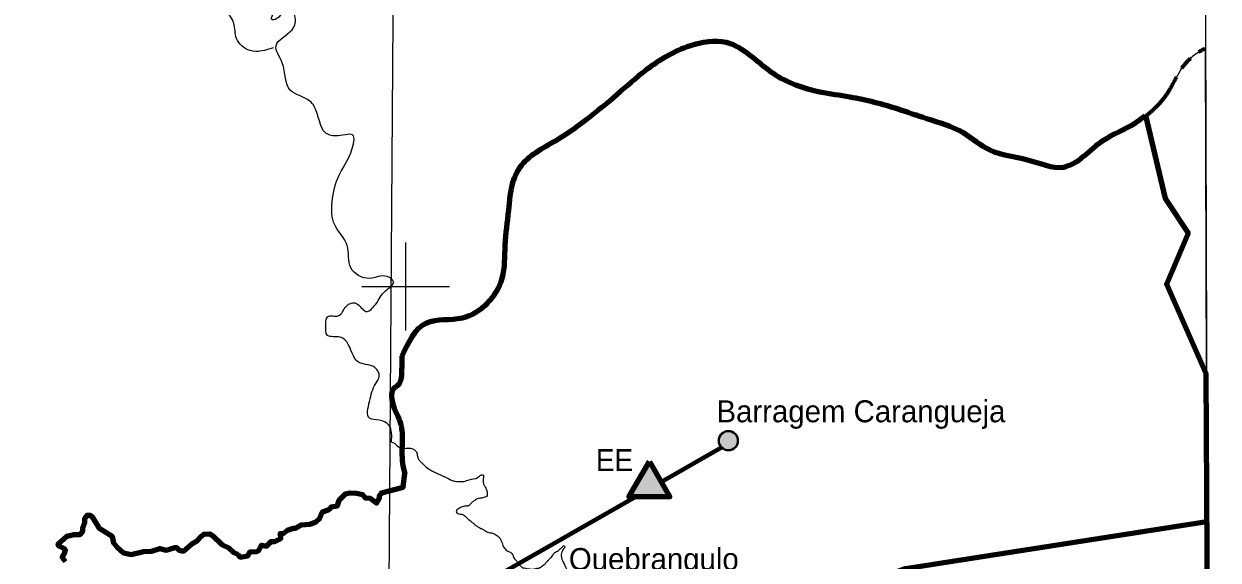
# Model space of a CAD drawing. Extents: x 553962 to 842807, y 8883888 to 9032388.
# Drawn here: x 766307 to 793496, y 8968776 to 8980977 of the extents above; entities that cross this region are included whole.
import ezdxf

# ---------------------------------------------------------------- set-up
doc = ezdxf.new("R2010")
doc.units = 0
doc.header["$LTSCALE"] = 200
doc.linetypes.add('LONG_DASH_SHORT_DASH', pattern=[9.9, 6, -1.2, 1.5, -1.2])
for name, color, linetype, lineweight in [('1', 7, 'Continuous', 13), ('2', 7, 'Continuous', 13), ('24', 7, 'Continuous', 25), ('28', 7, 'Continuous', 40), ('3', 7, 'Continuous', 13), ('41', 7, 'Continuous', 40), ('57', 7, 'Continuous', 13), ('7', 7, 'LONG_DASH_SHORT_DASH', 60), ('9', 7, 'Continuous', 90)]:
    doc.layers.add(name, color=color, linetype=linetype, lineweight=lineweight)

msp = doc.modelspace()

# ---------------------------------------------------------------- hatches: boundary and pattern name
at = {"layer": '28'}
msp.add_hatch(color=256, dxfattribs=at).paths.add_polyline_path([(780547.1, 8971019.7), (781013.2, 8970212.3), (780081, 8970212.3)])
at = {"layer": '41'}
msp.add_hatch(color=256, dxfattribs=at).paths.add_polyline_path([(782565, 8971494.2, 1), (782127.4, 8971494.2, 1)])

# ---------------------------------------------------------------- linework, layer by layer
at = {"layer": '1'}
msp.add_lwpolyline([(774987.1, 9020818), (774482.3, 8948876), (774053.6, 8890875.3)], dxfattribs=at)
at = {"layer": '2'}
for p, q in [((775000, 8974000), (775000, 8976000)), ((774000, 8975000), (776000, 8975000))]:
    msp.add_line(p, q, dxfattribs=at)
at = {"layer": '24'}
for points in [[(771983.6, 8980431.6), (771458.1, 8980369.7), (771148.9, 8980648.1), (771087.1, 8980988.4), (770932.5, 8981297.7), (770808.9, 8981638), (770345.2, 8981761.8), (770005.1, 8981885.5), (769819.6, 8982071.1), (769634.1, 8981854.6), (769479.5, 8982009.2), (769015.8, 8982318.6), (768923.1, 8982689.8), (768706.7, 8982937.2), (768593.5, 8983157.4), (768713.2, 8983415.3), (768842, 8983516.6), (768842, 8983590.2), (768630.3, 8983700.8), (768289.8, 8983940.2), (768207, 8984262.5), (768022.9, 8984465.2), (767700.8, 8984557.2), (767590.3, 8984640.1), (767553.5, 8985036.1), (767599.5, 8985266.4), (767599.5, 8985422.9), (767461.5, 8985607.1), (767314.2, 8985634.8), (767268.2, 8985533.4), (767139.4, 8985496.6), (766918.5, 8985616.3), (766789.6, 8985818.9), (766559.5, 8985957.1), (766219, 8986297.8), (765850.9, 8986500.4), (765363.1, 8986924.1), (764801.7, 8987504.3), (764663.6, 8987624), (764378.3, 8988066), (764295.5, 8988259.4), (764221.8, 8988296.3), (764083.8, 8988204.2), (763982.5, 8988268.6), (763669.6, 8988664.7), (763586.8, 8988683.1), (763540.8, 8988848.8), (763605.2, 8988913.3), (763665, 8988922.5), (763720.2, 8989088.3), (763554.6, 8989254.1), (763480.9, 8989475.1), (763628.2, 8989677.7), (763977.9, 8989935.6), (764143.6, 8990101.3), (764125.2, 8990285.5), (763849.1, 8990377.6), (763793.9, 8990525), (763591.4, 8990617.1), (763480.9, 8990635.5), (763260.1, 8990525), (763094.4, 8990525), (762965.5, 8990635.5), (762818.3, 8990856.5), (762781.5, 8990930.2), (762652.6, 8990967), (762450.1, 8991169.6), (762082, 8991335.4), (761916.3, 8991464.3), (761750.7, 8991464.3), (761640.2, 8991261.7), (761456.2, 8991059.1), (761382.5, 8990967), (761290.5, 8990948.6), (761198.5, 8991059.1), (761143.2, 8991298.6), (760867.1, 8991464.3), (760738.3, 8991666.9), (760499, 8991795.9), (760351.7, 8992035.3), (760094, 8992495.8), (759854.7, 8992403.7), (759652.3, 8992256.3), (759394.6, 8992477.3), (758971.2, 8992643.1), (758731.9, 8992753.6), (758639.9, 8993048.3), (758566.2, 8993324.6), (758695.1, 8993508.8), (758916, 8993453.6), (758879.2, 8993619.3)], [(774675.9, 8971457.7), (774621.3, 8971839.9), (774398.4, 8971961.6), (774175.5, 8972002.1), (774175.5, 8972387.4), (774317.3, 8972793), (774398.4, 8972955.3), (774297.1, 8973158.1), (773891.7, 8973300), (773810.7, 8973421.7), (773506.6, 8973847.6), (773222.9, 8973888.2), (773182.4, 8974151.8), (773222.9, 8974314), (773466.1, 8974334.3), (773648.5, 8974557.4), (773871.5, 8974618.2), (774094.4, 8974435.7), (774317.3, 8974598), (774540.3, 8974902.2), (774722.7, 8975105), (774580.8, 8975226.6), (774175.5, 8975186.1), (773749.8, 8975429.4), (773668.8, 8975936.4), (773385, 8976402.9), (773324.2, 8976930.1), (773486.4, 8977538.5), (773810.7, 8978248.3), (773810.7, 8978430.9), (773466.1, 8978430.9), (773182.4, 8978491.7), (772918.9, 8979100.1), (772817.6, 8979221.8), (772371.7, 8979465.1), (772189.3, 8980093.8), (772047.4, 8980479.1), (772412.2, 8980844.2), (772473, 8981168.7), (772331.2, 8981371.5), (772108.2, 8981128.1), (771966.3, 8981067.3), (772108.2, 8981452.6), (772189.3, 8981756.8), (772250.1, 8981979.9), (772392, 8982081.3), (772432.5, 8982324.6), (772229.8, 8982466.6), (772189.3, 8982730.2), (772432.5, 8982933), (772392, 8983196.7), (772250.1, 8983338.6), (772067.7, 8983500.8), (771824.5, 8983602.2), (771844.8, 8983865.9), (772432.5, 8984068.7), (772716.2, 8984109.2), (772979.7, 8984129.5), (773081, 8984332.3), (773486.4, 8984596), (773932.3, 8984839.3), (773932.3, 8985062.4), (773830.9, 8985244.9), (773830.9, 8985488.3), (774175.5, 8985812.8), (774337.6, 8985934.5), (774195.7, 8986117), (774114.7, 8986340.1), (773830.9, 8986299.5), (773668.8, 8986238.7), (773304, 8986380.6), (773141.8, 8986867.3), (773364.8, 8987475.7), (773405.3, 8987840.8), (773202.6, 8988205.8), (772939.2, 8988327.5), (772716.2, 8988570.8), (772777, 8988793.9), (773081, 8988854.8), (773324.2, 8988956.2), (773526.9, 8989098.1), (773385, 8989605.1), (773283.7, 8989970.2), (773000, 8990152.7), (772858.1, 8990436.6), (772979.7, 8990720.5), (772878.4, 8990761.1), (772493.3, 8990821.9), (772351.4, 8990963.9), (772047.4, 8991004.4), (771844.7, 8991166.7)], [(774675.9, 8971457.7), (774738.3, 8971438.3), (774783.6, 8971397.1), (774879.5, 8971329.9), (774915, 8971319.3), (775042.2, 8971323.1), (775133.7, 8971317), (775179.3, 8971301.3), (775209.5, 8971275.5), (775229.7, 8971255), (775254.7, 8971219.1)], [(775254.7, 8971219.1), (775273.9, 8971117.1), (775303.7, 8971055.7), (775353.9, 8970999.2), (775404.2, 8970952.9), (775434.4, 8970922), (775535.3, 8970844.6), (775616.1, 8970797.9), (775722.4, 8970745.9), (775793.2, 8970714.7), (775894.5, 8970667.8), (776066.5, 8970584.5), (776193.4, 8970562.8), (776239.2, 8970562.3), (776325.7, 8970566.5), (776448.3, 8970605.9), (776637.1, 8970654.8), (776678.1, 8970684.9), (776724.2, 8970715), (776770, 8970709.4), (776769.4, 8970663.6), (776763.5, 8970587.3), (776772.7, 8970505.8), (776802.6, 8970449.5), (776837.4, 8970377.9), (776857, 8970311.6), (776856.6, 8970275.9), (776840.7, 8970225.2), (776804.9, 8970205.2), (776713.1, 8970185.8), (776631.5, 8970171.4), (776554.6, 8970121.4), (776498.2, 8970081.2), (776456.9, 8970030.8), (776395.6, 8970006), (776339.6, 8970001.5), (776242.6, 8969966.9), (776211.8, 8969952), (776149.9, 8969876.3), (776186.5, 8969836.6), (776239.8, 8969823.2), (776312, 8969808.4), (776352.3, 8969777.4), (776513.4, 8969633.2), (776568.9, 8969586.9), (776644.6, 8969535.2), (776674.9, 8969519.6), (776695.1, 8969499), (776700.1, 8969499), (776760.9, 8969472.9), (776821.5, 8969431.5), (776867, 8969410.7), (776978.7, 8969389.1), (777074.7, 8969337.2), (777125.2, 8969296)], [(777125.2, 8969296), (777150.2, 8969265.2), (777165.1, 8969229.4), (777194.9, 8969168), (777209.5, 8969106.8), (777234.5, 8969070.9), (777269.6, 8969024.7), (777309.9, 8968988.7), (777365.5, 8968962.7), (777416, 8968926.5), (777445.9, 8968875.3), (777460.7, 8968829.3), (777540.9, 8968731.8), (777570.9, 8968685.7), (777626.2, 8968629.1), (777656.5, 8968603.3), (777697.1, 8968597.8), (777752.9, 8968582), (777819, 8968576.2), (777864.7, 8968570.6), (777981.9, 8968589.7), (778007.3, 8968589.5), (778053.3, 8968604.2), (778130.3, 8968664.5), (778171.3, 8968694.6), (778197.1, 8968724.9), (778212.6, 8968740), (778258.9, 8968790.4), (778315.5, 8968845.8), (778346.6, 8968891.2), (778393, 8968946.7), (778474.9, 8968991.7), (778495.4, 8969006.7), (778521.2, 8969037), (778536.6, 8969047), (778557.1, 8969062), (778577.8, 8969092.3), (778608.4, 8969102.2), (778623.4, 8969076.6), (778582.1, 8969021.1), (778556, 8968965.3), (778540, 8968904.5), (778569, 8968766.7), (778613.7, 8968674.7), (778663.3, 8968567.3), (778708.2, 8968490.5), (778732.7, 8968403.7), (778736.9, 8968327.3), (778736.2, 8968266.2), (778745.1, 8968154.2), (778744.1, 8968062.6), (778748.6, 8968016.8), (778747.8, 8967945.5), (778762.2, 8967874.1), (778787.1, 8967823)]]:
    msp.add_spline(points, degree=3, dxfattribs=at)
at = {"layer": '28', "lineweight": 80}
msp.add_line((780834.5, 8970568.3), (782179.4, 8971337.2), dxfattribs=at)
at = {"layer": '28', "lineweight": 90}
msp.add_lwpolyline([(780547.1, 8971019.7), (781013.2, 8970212.3), (780081, 8970212.3)], close=True, dxfattribs=at)
at = {"layer": '28', "lineweight": 80}
msp.add_lwpolyline([(770852.1, 8963774.6), (772648.5, 8965392.4), (773355.1, 8966292.3), (780250.8, 8970234.6)], dxfattribs=at)
at = {"layer": '3', "lineweight": 25}
msp.add_lwpolyline([(563033.9, 9026438.8), (793061.1, 9026438.8), (793495.6, 8889836.8), (563468.3, 8889836.8)], close=True, dxfattribs=at)
at = {"layer": '41'}
msp.add_circle((782346.2, 8971494.2), 218.8, dxfattribs=at)
at = {"layer": '57', "lineweight": 90}
for p, q in [((791827.7, 8978880.8), (791843.8, 8978894.3)), ((774916.5, 8973418.2), (774916.5, 8973418.2))]:
    msp.add_line(p, q, dxfattribs=at)
at = {"layer": '57'}
msp.add_lwpolyline([(791861.2, 8978909.1), (792308, 8977021.4), (792832.9, 8976230), (792341.4, 8975070.9), (793231, 8973036.1), (793207.5, 8980426.2)], dxfattribs=at)
at = {"layer": '57', "lineweight": 25}
for points in [[(791843.8, 8978894.3), (792290.6, 8977006.6), (792815.5, 8976215.2), (792324, 8975056.1), (793213.6, 8973021.3)], [(771181.1, 8968911.9), (771232.2, 8968842.1), (771403.7, 8968873.3), (771403.7, 8968873.3), (771458.9, 8968967.1), (771607.7, 8968969.9), (771652.6, 8968991.1), (771717.4, 8969119.8), (771834.2, 8969096.5), (771935.9, 8969198.1), (772018.4, 8969202.2), (772155.3, 8969264.8), (772159.1, 8969321.5), (772140.8, 8969382.4), (772226.6, 8969390.3), (772308.9, 8969456.7), (772446.2, 8969501.6), (772474.6, 8969493.3), (772618.1, 8969576.7), (772815.2, 8969593.9), (772944.1, 8969641.2), (773047, 8969731.2), (773102.9, 8969872.7), (773255, 8969928.6), (773300.2, 8969990.6), (773443.7, 8970014.5), (773486.8, 8970139.8), (773626, 8970282.5), (773731.8, 8970306), (773871, 8970302.2), (774013.6, 8970267), (774078.7, 8970194.6), (774183.8, 8970183.7), (774331.7, 8970068.2), (774400.2, 8970183.1), (774404.4, 8970245.9), (774447.5, 8970308.5), (774942, 8970436.7), (774983.4, 8970753.6)], [(767257.5, 8968745.1), (767180.2, 8968833.8), (767230, 8968925.1), (767251.4, 8969001.3), (767220.2, 8969040.4), (767106.6, 8969091.4), (767091, 8969146.1), (767283.1, 8969319.4), (767449.7, 8969360.5), (767587.1, 8969360.8), (767645.6, 8969438.8), (767649.7, 8969517), (767696.7, 8969642.2), (767696.8, 8969728.3), (767747.7, 8969798.6), (767806.5, 8969798.6), (767865.2, 8969759.6), (768016.5, 8969507.1), (768313.9, 8969319.5), (768350.3, 8969169.2), (768422.8, 8969081.5), (768576.7, 8968943.6), (768753.5, 8968906.8), (769027.6, 8968973.2), (769212.3, 8968980.6), (769403.2, 8969038.4), (769546.6, 8969001.4), (769742.5, 8969063.8), (769785.4, 8969059.9), (769844.5, 8969001.3), (769938.3, 8968981.8), (770128.5, 8969144.1), (770257.8, 8969222.4), (770348, 8969324.1), (770402.7, 8969363), (770539.7, 8969371), (770598.9, 8969335.8), (770812.7, 8969130.4), (770975.1, 8969053.6), (771089, 8968946.3), (771181.1, 8968911.9)]]:
    msp.add_lwpolyline(points, dxfattribs=at)
at = {"layer": '57', "lineweight": 90}
for points in [[(791843.8, 8978894.3), (792290.6, 8977006.6), (792815.5, 8976215.2), (792324, 8975056.1), (793213.6, 8973021.3), (793248.2, 8967604.7)], [(771181.1, 8968911.9), (771232.2, 8968842.1), (771403.7, 8968873.3), (771403.7, 8968873.3), (771458.9, 8968967.1), (771607.7, 8968969.9), (771652.6, 8968991.1), (771717.4, 8969119.8), (771834.2, 8969096.5), (771935.9, 8969198.1), (772018.4, 8969202.2), (772155.3, 8969264.8), (772159.1, 8969321.5), (772140.8, 8969382.4), (772226.6, 8969390.3), (772308.9, 8969456.7), (772446.2, 8969501.6), (772474.6, 8969493.3), (772618.1, 8969576.7), (772815.2, 8969593.9), (772944.1, 8969641.2), (773047, 8969731.2), (773102.9, 8969872.7), (773255, 8969928.6), (773300.2, 8969990.6), (773443.7, 8970014.5), (773486.8, 8970139.8), (773626, 8970282.5), (773731.8, 8970306), (773871, 8970302.2), (774013.6, 8970267), (774078.7, 8970194.6), (774183.8, 8970183.7), (774331.7, 8970068.2), (774400.2, 8970183.1), (774404.4, 8970245.9), (774447.5, 8970308.5), (774942, 8970436.7), (774983.4, 8970753.6), (774985.7, 8970742.8)], [(767257.5, 8968745.1), (767180.2, 8968833.8), (767230, 8968925.1), (767251.4, 8969001.3), (767220.2, 8969040.4), (767106.6, 8969091.4), (767091, 8969146.1), (767283.1, 8969319.4), (767449.7, 8969360.5), (767587.1, 8969360.8), (767645.6, 8969438.8), (767649.7, 8969517), (767696.7, 8969642.2), (767696.8, 8969728.3), (767747.7, 8969798.6), (767806.5, 8969798.6), (767865.2, 8969759.6), (768016.5, 8969507.1), (768313.9, 8969319.5), (768350.3, 8969169.2), (768422.8, 8969081.5), (768576.7, 8968943.6), (768753.5, 8968906.8), (769027.6, 8968973.2), (769212.3, 8968980.6), (769403.2, 8969038.4), (769546.6, 8969001.4), (769742.5, 8969063.8), (769785.4, 8969059.9), (769844.5, 8969001.3), (769938.3, 8968981.8), (770128.5, 8969144.1), (770257.8, 8969222.4), (770348, 8969324.1), (770402.7, 8969363), (770539.7, 8969371), (770598.9, 8969335.8), (770812.7, 8969130.4), (770975.1, 8969053.6), (771089, 8968946.3), (771181.1, 8968911.9)]]:
    msp.add_lwpolyline(points, dxfattribs=at)
at = {"layer": '57', "lineweight": 25}
for points in [[(774916.5, 8973418.2), (775478.1, 8974177.4), (776290.7, 8974291.4), (777196.8, 8975186), (777264.6, 8975941.4), (777345.8, 8976735), (777449.2, 8977387.2), (777608.6, 8977717.9), (778406.9, 8978319.4), (779810.2, 8979372), (780468.2, 8979924.8), (781480.7, 8980484.1), (782292.3, 8980559.6), (783352.2, 8979861.4), (784430.9, 8979432.1), (785111.7, 8979317.6), (786206.5, 8979042), (786859.7, 8978825.3), (787687.7, 8978503.1), (788298.8, 8978107.6), (789154.5, 8977887.5), (789973.3, 8977719.2), (790885.7, 8978331.6), (791603.1, 8978716.6), (791827.7, 8978880.8)], [(774985.7, 8970742.8), (774935.6, 8970978.9), (774927.1, 8971504.1), (774899.9, 8971837.9), (774747.8, 8972226.8), (774763.5, 8972712.9), (774815.3, 8972749.7), (774914.1, 8973066.6), (774916.5, 8973418.2)]]:
    msp.add_spline(points, degree=3, dxfattribs=at)
at = {"layer": '57', "lineweight": 90}
for points in [[(774916.5, 8973418.2), (775478.1, 8974177.4), (776290.7, 8974291.4), (777196.8, 8975186), (777264.6, 8975941.4), (777345.8, 8976735), (777449.2, 8977387.2), (777608.6, 8977717.9), (778406.9, 8978319.4), (779810.2, 8979372), (780468.2, 8979924.8), (781480.7, 8980484.1), (782292.3, 8980559.6), (783352.2, 8979861.4), (784430.9, 8979432.1), (785111.7, 8979317.6), (786206.5, 8979042), (786859.7, 8978825.3), (787687.7, 8978503.1), (788298.8, 8978107.6), (789154.5, 8977887.5), (789973.3, 8977719.2), (790885.7, 8978331.6), (791603.1, 8978716.6), (791827.7, 8978880.8)], [(774985.7, 8970742.8), (774935.6, 8970978.9), (774927.1, 8971504.1), (774899.9, 8971837.9), (774747.8, 8972226.8), (774763.5, 8972712.9), (774815.3, 8972749.7), (774914.1, 8973066.6), (774916.5, 8973418.2)]]:
    msp.add_spline(points, degree=3, dxfattribs=at)
at = {"layer": '57'}
msp.add_spline([(793207.5, 8980426.2), (793070.1, 8980345.1), (792695.4, 8980005.5), (792379.3, 8979459.6), (791843.8, 8978894.3)], degree=3, dxfattribs=at)
at = {"layer": '7'}
for points in [[(771181.1, 8968911.9), (771232.2, 8968842.1), (771403.7, 8968873.3), (771403.7, 8968873.3), (771458.9, 8968967.1), (771607.7, 8968969.9), (771652.6, 8968991.1), (771717.4, 8969119.8), (771834.2, 8969096.5), (771935.9, 8969198.1), (772018.4, 8969202.2), (772155.3, 8969264.8), (772159.1, 8969321.5), (772140.8, 8969382.4), (772226.6, 8969390.3), (772308.9, 8969456.7), (772446.2, 8969501.6), (772474.6, 8969493.3), (772618.1, 8969576.7), (772815.2, 8969593.9), (772944.1, 8969641.2), (773047, 8969731.2), (773102.9, 8969872.7), (773255, 8969928.6), (773300.2, 8969990.6), (773443.7, 8970014.5), (773486.8, 8970139.8), (773626, 8970282.5), (773731.8, 8970306), (773871, 8970302.2), (774013.6, 8970267), (774078.7, 8970194.6), (774183.8, 8970183.7), (774331.7, 8970068.2), (774400.2, 8970183.1), (774404.4, 8970245.9), (774447.5, 8970308.5), (774942, 8970436.7), (774983.4, 8970753.6)], [(771181.1, 8968911.9), (771232.2, 8968842.1), (771403.7, 8968873.3), (771403.7, 8968873.3), (771458.9, 8968967.1), (771607.7, 8968969.9), (771652.6, 8968991.1), (771717.4, 8969119.8), (771834.2, 8969096.5), (771935.9, 8969198.1), (772018.4, 8969202.2), (772155.3, 8969264.8), (772159.1, 8969321.5), (772140.8, 8969382.4), (772226.6, 8969390.3), (772308.9, 8969456.7), (772446.2, 8969501.6), (772474.6, 8969493.3), (772618.1, 8969576.7), (772815.2, 8969593.9), (772944.1, 8969641.2), (773047, 8969731.2), (773102.9, 8969872.7), (773255, 8969928.6), (773300.2, 8969990.6), (773443.7, 8970014.5), (773486.8, 8970139.8), (773626, 8970282.5), (773731.8, 8970306), (773871, 8970302.2), (774013.6, 8970267), (774078.7, 8970194.6), (774183.8, 8970183.7), (774331.7, 8970068.2), (774400.2, 8970183.1), (774404.4, 8970245.9), (774447.5, 8970308.5), (774942, 8970436.7), (774983.4, 8970753.6)], [(767257.5, 8968745.1), (767180.2, 8968833.8), (767230, 8968925.1), (767251.4, 8969001.3), (767220.2, 8969040.4), (767106.6, 8969091.4), (767091, 8969146.1), (767283.1, 8969319.4), (767449.7, 8969360.5), (767587.1, 8969360.8), (767645.6, 8969438.8), (767649.7, 8969517), (767696.7, 8969642.2), (767696.8, 8969728.3), (767747.7, 8969798.6), (767806.5, 8969798.6), (767865.2, 8969759.6), (768016.5, 8969507.1), (768313.9, 8969319.5), (768350.3, 8969169.2), (768422.8, 8969081.5), (768576.7, 8968943.6), (768753.5, 8968906.8), (769027.6, 8968973.2), (769212.3, 8968980.6), (769403.2, 8969038.4), (769546.6, 8969001.4), (769742.5, 8969063.8), (769785.4, 8969059.9), (769844.5, 8969001.3), (769938.3, 8968981.8), (770128.5, 8969144.1), (770257.8, 8969222.4), (770348, 8969324.1), (770402.7, 8969363), (770539.7, 8969371), (770598.9, 8969335.8), (770812.7, 8969130.4), (770975.1, 8969053.6), (771089, 8968946.3), (771181.1, 8968911.9)]]:
    msp.add_lwpolyline(points, dxfattribs=at)
for points in [[(774916.5, 8973418.2), (775478.1, 8974177.4), (776290.7, 8974291.4), (777196.8, 8975186), (777264.6, 8975941.4), (777345.8, 8976735), (777449.2, 8977387.2), (777608.6, 8977717.9), (778406.9, 8978319.4), (779810.2, 8979372), (780468.2, 8979924.8), (781480.7, 8980484.1), (782292.3, 8980559.6), (783352.2, 8979861.4), (784430.9, 8979432.1), (785111.7, 8979317.6), (786206.5, 8979042), (786859.7, 8978825.3), (787687.7, 8978503.1), (788298.8, 8978107.6), (789154.5, 8977887.5), (789973.3, 8977719.2), (790885.7, 8978331.6), (791603.1, 8978716.6), (792379.3, 8979459.6), (792695.4, 8980005.5), (793070.1, 8980345.1), (793207.5, 8980426.2)], [(774916.5, 8973418.2), (775478.1, 8974177.4), (776290.7, 8974291.4), (777196.8, 8975186), (777264.6, 8975941.4), (777345.8, 8976735), (777449.2, 8977387.2), (777608.6, 8977717.9), (778406.9, 8978319.4), (779810.2, 8979372), (780468.2, 8979924.8), (781480.7, 8980484.1), (782292.3, 8980559.6), (783352.2, 8979861.4), (784430.9, 8979432.1), (785111.7, 8979317.6), (786206.5, 8979042), (786859.7, 8978825.3), (787687.7, 8978503.1), (788298.8, 8978107.6), (789154.5, 8977887.5), (789973.3, 8977719.2), (790885.7, 8978331.6), (791603.1, 8978716.6), (791827.7, 8978880.8)], [(774916.5, 8973418.2), (775478.1, 8974177.4), (776290.7, 8974291.4), (777196.8, 8975186), (777264.6, 8975941.4), (777345.8, 8976735), (777449.2, 8977387.2), (777608.6, 8977717.9), (778406.9, 8978319.4), (779810.2, 8979372), (780468.2, 8979924.8), (781480.7, 8980484.1), (782292.3, 8980559.6), (783352.2, 8979861.4), (784430.9, 8979432.1), (785111.7, 8979317.6), (786206.5, 8979042), (786859.7, 8978825.3), (787687.7, 8978503.1), (788298.8, 8978107.6), (789154.5, 8977887.5), (789973.3, 8977719.2), (790885.7, 8978331.6), (791603.1, 8978716.6), (791827.7, 8978880.8)], [(774985.7, 8970742.8), (774935.6, 8970978.9), (774927.1, 8971504.1), (774899.9, 8971837.9), (774747.8, 8972226.8), (774763.5, 8972712.9), (774815.3, 8972749.7), (774914.1, 8973066.6), (774916.5, 8973418.2)]]:
    msp.add_spline(points, degree=3, dxfattribs=at)
at = {"layer": '9'}
msp.add_lwpolyline([(776094.3, 8958996), (782123.9, 8965418.5), (782863.1, 8965941.5), (783480.4, 8966997.7), (783430.8, 8967124.9), (783358, 8967480.3), (786382.1, 8968583.5), (793241.7, 8969653.8)], dxfattribs=at)
msp.add_lwpolyline([(776094.3, 8958996), (782123.9, 8965418.5), (782863.1, 8965941.5), (783480.4, 8966997.7), (783430.8, 8967124.9), (783358, 8967480.3), (786382.1, 8968583.5), (793241.7, 8969653.8)], dxfattribs=at)

# ---------------------------------------------------------------- texts
at = {"layer": '41'}
for s, p in [('Barragem Carangueja', (782075.5, 8971912.4)), ('Quebrangulo', (778715.4, 8968550.1))]:
    msp.add_text(s, height=500, dxfattribs=at).set_placement(p)
at = {"layer": '41', "width": 0.95}
msp.add_text('EE', height=500, dxfattribs=at).set_placement((779330.2, 8970801.3))

doc.saveas('drawing.dxf')
